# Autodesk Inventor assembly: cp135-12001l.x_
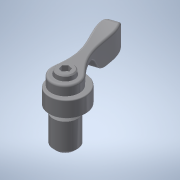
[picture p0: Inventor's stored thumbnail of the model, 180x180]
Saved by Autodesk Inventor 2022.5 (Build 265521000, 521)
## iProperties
Part Number: cp135-12001l.x_
Material: 一般
Document SubType Name: Assembly
Designer: ImaoCorp
Sending System: SOLIDWORKS 2017-2017317
MC: AMD64
MC_MODEL: Intel64 Family 6 Model 60 Stepping 3, GenuineIntel
OS: Windows_NT
FRU: Parasolid Version 29.0, build 201,  4-17-2017
FORMAT: text
GUISE: transmit
KEY: cp135-12001l
FILE: cp135-12001l.x_t
DATE: Thu Apr 04 16:37:54 2019
Author: ImaoCorp
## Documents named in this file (3)
- X:\14_SW2022-Inv2022\00_全2023-1023新製品(TCC)まで\c\cp135-12001l\CP135-12001L.iam
- X:\14_SW2022-Inv2022\00_全2023-1023新製品(TCC)まで\c\cp135-12001l\cp135-12001l_01.ipt
- X:\14_SW2022-Inv2022\00_全2023-1023新製品(TCC)まで\c\cp135-12001l\cp135-12001l_02.ipt
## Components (2 placed, 2 different names)
1. cp135-12001l_01
2. cp135-12001l_02
